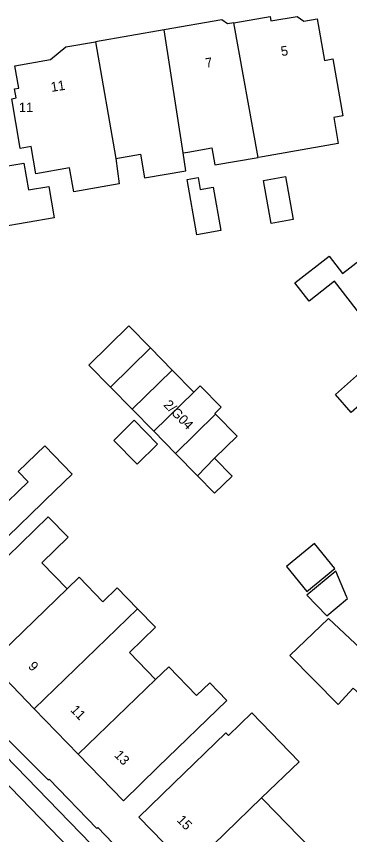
# Model space of a CAD drawing. Extents: x 161772 to 163123, y 383092 to 383917.
# Drawn here: x 162184.4 to 162219, y 383398.5 to 383483.6 of the extents above; entities that cross this region are included whole.
import ezdxf

# ---------------------------------------------------------------- set-up
doc = ezdxf.new("R2010")
doc.units = 0
for name, color, linetype in [('IMGEO_Pand', 7, 'Continuous'), ('IMGEO_Pand_nummerreeks', 7, 'Continuous'), ('IMGEO_Rijbaan_lokaal_open', 7, 'Continuous'), ('IMGEO_Voetpad_gesloten', 7, 'Continuous')]:
    doc.layers.add(name, color=color, linetype=linetype)

msp = doc.modelspace()

# ---------------------------------------------------------------- linework, layer by layer
at = {"layer": 'IMGEO_Pand'}
for points in [[(162207.005, 383482.894), (162210.769, 383483.544), (162210.849, 383483.078), (162213.59, 383483.551), (162214.28, 383483.065), (162215.666, 383483.304), (162216.414, 383478.976), (162217.307, 383479.131), (162218.333, 383473.195), (162217.382, 383473.031), (162217.851, 383470.318), (162212.924, 383469.467), (162209.977, 383468.958), (162209.524, 383468.88)], [(162207.005, 383482.894), (162206.345, 383482.78), (162205.781, 383483.178), (162199.788, 383482.143)], [(162209.524, 383468.88), (162207.005, 383482.894)], [(162199.788, 383482.143), (162192.649, 383480.909)], [(162201.743, 383469.351), (162199.788, 383482.143)], [(162194.743, 383468.782), (162195.103, 383466.119), (162190.379, 383465.302), (162189.948, 383467.795), (162186.432, 383467.187), (162185.943, 383470.02), (162184.829, 383469.827), (162184.789, 383470.06), (162183.938, 383474.987), (162184.39, 383475.065), (162184.228, 383476.005), (162184.662, 383476.08), (162184.258, 383478.419), (162187.975, 383479.061), (162189.551, 383480.374), (162192.649, 383480.909)], [(162192.649, 383480.909), (162194.743, 383468.782)], [(162201.743, 383469.351), (162202.215, 383469.433), (162204.722, 383469.866), (162205.027, 383468.102), (162209.524, 383468.88)], [(162194.743, 383468.782), (162197.321, 383469.228), (162197.746, 383466.766), (162202.025, 383467.505), (162201.743, 383469.351)], [(162181.658, 383467.691), (162185.208, 383468.293), (162185.681, 383465.503), (162187.801, 383465.863), (162188.356, 383462.59), (162182.727, 383461.637), (162182.16, 383464.99)], [(162202.171, 383466.598), (162203.292, 383466.792), (162203.504, 383465.563), (162204.864, 383465.798), (162205.646, 383461.269), (162203.165, 383460.84), (162202.171, 383466.598)], [(162210.097, 383466.488), (162212.372, 383466.89), (162213.161, 383462.427), (162210.886, 383462.025), (162210.097, 383466.488)], [(162223.153, 383448.667), (162217.472, 383455.999), (162214.824, 383453.948), (162213.354, 383455.845), (162216.911, 383458.6), (162218.307, 383456.797), (162220.148, 383458.223), (162220.503, 383457.764), (162224.392, 383460.777), (162224.636, 383460.46), (162225.394, 383461.047), (162225.571, 383460.817), (162227.318, 383462.17), (162229.917, 383458.815), (162230.752, 383458.709), (162231.773, 383457.391), (162231.663, 383456.518), (162232.26, 383455.747)], [(162194.201, 383444.995), (162191.95, 383447.294), (162196.103, 383451.36), (162198.352, 383449.067)], [(162194.201, 383444.995), (162198.352, 383449.067)], [(162198.352, 383449.067), (162200.601, 383446.774)], [(162200.601, 383446.774), (162196.448, 383442.7)], [(162202.85, 383444.481), (162200.601, 383446.774)], [(162217.557, 383444.234), (162221.015, 383447.277), (162222.654, 383445.414), (162219.196, 383442.371), (162217.557, 383444.234)], [(162205.099, 383442.188), (162205.025, 383442.264), (162205.703, 383442.929), (162203.527, 383445.145), (162202.85, 383444.481)], [(162196.448, 383442.7), (162194.201, 383444.995)], [(162198.696, 383440.406), (162202.85, 383444.481)], [(162196.448, 383442.7), (162198.696, 383440.406)], [(162200.943, 383438.111), (162205.099, 383442.188)], [(162205.099, 383442.188), (162207.349, 383439.896), (162205.016, 383437.608)], [(162196.962, 383436.989), (162194.539, 383439.462), (162196.668, 383441.549), (162199.092, 383439.076), (162196.962, 383436.989)], [(162198.696, 383440.406), (162200.943, 383438.111)], [(162178.946, 383435.729), (162181.519, 383433.072), (162182.471, 383432.089), (162185.629, 383435.146), (162184.589, 383436.22), (162187.362, 383438.904), (162190.226, 383435.946), (162187.453, 383433.262), (162187.114, 383432.933), (162183.521, 383429.455), (162182.736, 383430.266), (162175.122, 383422.894), (162170.557, 383427.608)], [(162203.229, 383435.777), (162200.943, 383438.111)], [(162205.016, 383437.608), (162206.836, 383435.754), (162205.006, 383433.962), (162203.229, 383435.777)], [(162203.229, 383435.777), (162205.016, 383437.608)], [(162181.695, 383416.284), (162177.012, 383421.121), (162180.573, 383424.569), (162187.733, 383431.502), (162189.787, 383429.38), (162187.059, 383426.739), (162189.691, 383424.021)], [(162214.597, 383423.738), (162217.517, 383426.131), (162215.386, 383428.732), (162212.466, 383426.339), (162214.597, 383423.738)], [(162218.804, 383423.001), (162218.714, 383423.219), (162217.623, 383425.855), (162214.597, 383423.357), (162216.657, 383421.228), (162218.804, 383423.001)], [(162189.691, 383424.021), (162190.939, 383425.229), (162193.403, 383422.684), (162194.9, 383424.133), (162197.011, 383421.953)], [(162181.695, 383416.284), (162189.691, 383424.021)], [(162197.011, 383421.953), (162186.273, 383411.556)], [(162197.011, 383421.953), (162198.881, 383420.022), (162196.161, 383417.389), (162198.874, 383414.587)], [(162222.952, 383415.224), (162216.858, 383420.926), (162212.824, 383417.089), (162217.843, 383412.003), (162219.391, 383413.699), (162220.502, 383412.684), (162222.952, 383415.224)], [(162186.273, 383411.556), (162181.695, 383416.284)], [(162190.853, 383406.825), (162195.537, 383401.988), (162199.13, 383405.466), (162206.29, 383412.399), (162204.51, 383414.236), (162203.144, 383412.913), (162200.242, 383415.91), (162198.874, 383414.587)], [(162198.874, 383414.587), (162190.853, 383406.825)], [(162190.853, 383406.825), (162186.273, 383411.556)], [(162209.898, 383402.282), (162213.814, 383406.034), (162208.882, 383411.127), (162206.446, 383408.769), (162206.182, 383409.042), (162200.737, 383403.77), (162197.144, 383400.291), (162202.321, 383394.945)], [(162202.321, 383394.945), (162207.432, 383389.666), (162211.025, 383393.144), (162215.009, 383397.002), (162210.107, 383402.066), (162209.898, 383402.282)], [(162209.898, 383402.282), (162202.321, 383394.945)]]:
    msp.add_lwpolyline(points, dxfattribs=at)
at = {"layer": 'IMGEO_Rijbaan_lokaal_open'}
msp.add_lwpolyline([(162227.035, 383358.663), (162144.674, 383443.797)], dxfattribs=at)
at = {"layer": 'IMGEO_Voetpad_gesloten'}
for points in [[(162124.151, 383469.777), (162146.748, 383446.299), (162164.511, 383427.931), (162164.384, 383427.827), (162167.143, 383425.007), (162167.165, 383425.116), (162173.798, 383418.361), (162173.894, 383418.482), (162182.621, 383409.404), (162182.533, 383409.335), (162187.734, 383404.146), (162187.816, 383404.232), (162192.761, 383399.098), (162192.872, 383399.214), (162225.52, 383365.058), (162237.143, 383353.041), (162243.372, 383346.601)], [(162146.078, 383445.121), (162166.479, 383423.941), (162202.24, 383387.094), (162228.36, 383359.913)]]:
    msp.add_lwpolyline(points, dxfattribs=at)

# ---------------------------------------------------------------- texts
at = {"layer": 'IMGEO_Pand_nummerreeks'}
for s, rotation, p in [('5', 8.84059, (162211.972, 383479.41)), ('7', 8.84074, (162204.12, 383478.19)), ('11', 8.84059, (162188.074, 383475.693)), ('2/G04', 314.24932, (162199.644, 383443.09)), ('9', 314.07743, (162185.577, 383415.897)), ('11', 314.07502, (162189.968, 383411.362)), ('13', 314.07743, (162194.52, 383406.661)), ('15', 314.07743, (162201.014, 383399.916))]:
    msp.add_text(s, height=1, rotation=rotation, dxfattribs=at).set_placement(p)
msp.add_text('11', height=1, dxfattribs=at).set_placement((162184.68, 383473.589))

doc.saveas('drawing.dxf')
